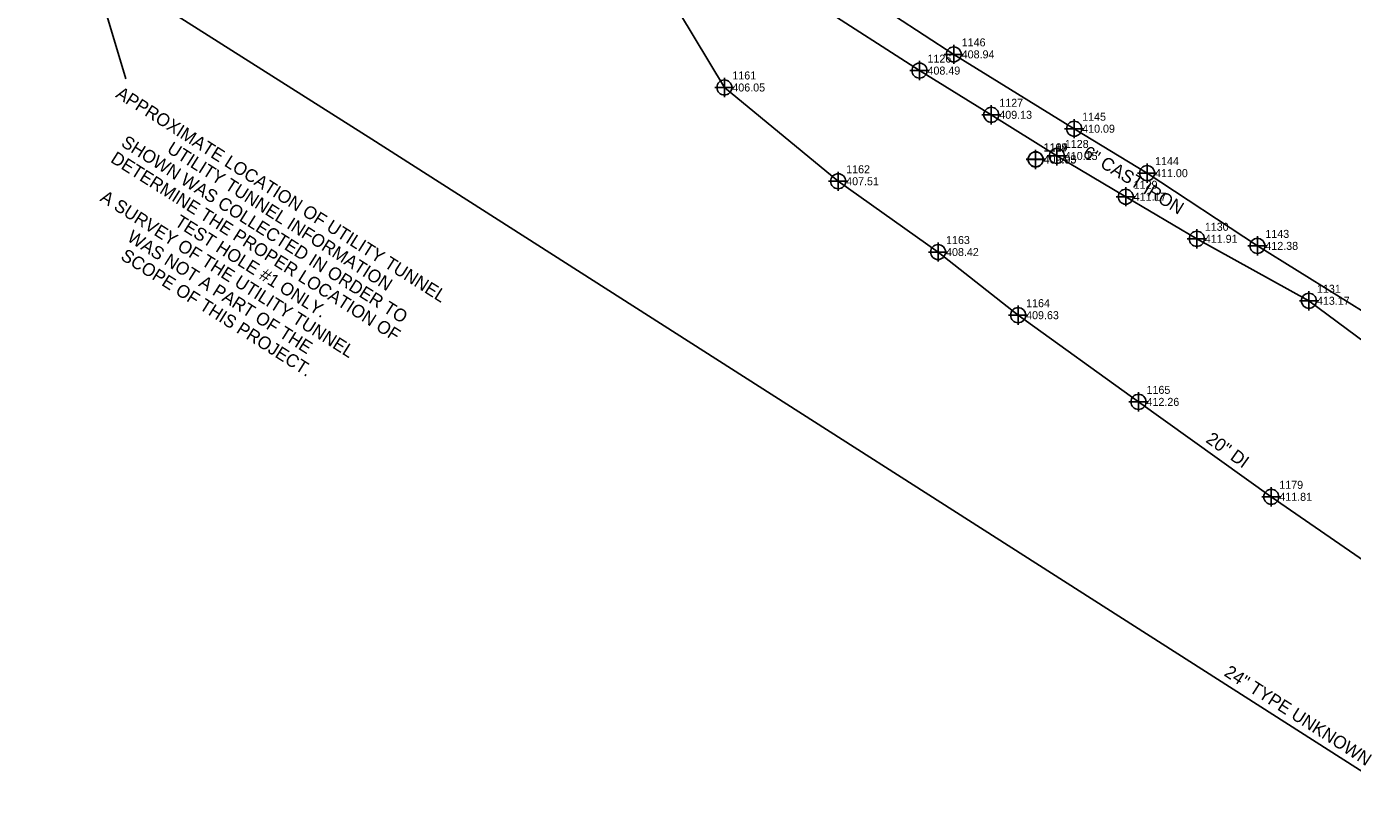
# Model space of a CAD drawing. Extents: x 2024146 to 2025516, y 819906 to 820765.
# Drawn here: x 2024645.2 to 2025059.4, y 820076.1 to 820314.8 of the extents above; entities that cross this region are included whole.
import ezdxf

# ---------------------------------------------------------------- set-up
doc = ezdxf.new("R2010")
doc.units = 0
for name, color, linetype in [('Prop Conc 4in Sidewalk', 7, 'Continuous'), ('Prop DSN Text', 7, 'Continuous'), ('Prop Lane Lines', 7, 'Continuous'), ('Sheet Block Revision CELL', 7, 'Continuous'), ('Sheet Data Field CELL', 7, 'Continuous'), ('Sheet Layout Plan Border', 7, 'Continuous'), ('Sheet Layout Profile Border Port 2', 7, 'Continuous'), ('Sheet Plan And Profile CELL', 7, 'Continuous'), ('Sheet Plot Border Inside CELL', 7, 'Continuous'), ('Sheet Plot Border Outside CELL', 7, 'Continuous'), ('Sheet Profile Grid Minor CELL', 7, 'Continuous')]:
    doc.layers.add(name, color=color, linetype=linetype)

msp = doc.modelspace()

# ---------------------------------------------------------------- linework, layer by layer
at = {"layer": 'Prop Lane Lines'}
msp.add_lwpolyline([(2024566.33, 820397.9), (2024753.12, 820279.6), (2025069.15, 820077.77), (2025141.71, 820076.11)], dxfattribs=at)
at = {"layer": 'Sheet Layout Plan Border'}
for points in [[(2024934.85, 820309.1), (2024934.85, 820306.1)], [(2024924.16, 820304.03), (2024924.16, 820301.03)], [(2024931.85, 820306.1), (2024934.85, 820306.1)], [(2024934.85, 820306.1), (2024937.85, 820306.1)], [(2024934.85, 820306.1), (2024934.85, 820303.1)], [(2024921.16, 820301.03), (2024924.16, 820301.03)], [(2024924.16, 820301.03), (2024927.16, 820301.03)], [(2024924.16, 820301.03), (2024924.16, 820298.03)], [(2024860.2, 820295.75), (2024863.2, 820295.75)], [(2024863.2, 820298.75), (2024863.2, 820295.75)], [(2024863.2, 820295.75), (2024866.2, 820295.75)], [(2024863.2, 820295.75), (2024863.2, 820292.75)], [(2024943.59, 820287.22), (2024946.59, 820287.22)], [(2024946.59, 820290.22), (2024946.59, 820287.22)], [(2024946.59, 820287.22), (2024949.59, 820287.22)], [(2024946.59, 820287.22), (2024946.59, 820284.22)], [(2024969.48, 820282.87), (2024972.48, 820282.87)], [(2024972.48, 820285.87), (2024972.48, 820282.87)], [(2024972.48, 820282.87), (2024975.48, 820282.87)], [(2024972.48, 820282.87), (2024972.48, 820279.87)], [(2024960.44, 820276.32), (2024960.44, 820273.32)], [(2024960.44, 820276.24), (2024960.44, 820273.24)], [(2024960.45, 820276.32), (2024960.45, 820273.32)], [(2024967.06, 820277.36), (2024967.06, 820274.36)], [(2024957.44, 820273.32), (2024960.44, 820273.32)], [(2024957.44, 820273.24), (2024960.44, 820273.24)], [(2024957.45, 820273.32), (2024960.45, 820273.32)], [(2024960.44, 820273.32), (2024963.44, 820273.32)], [(2024960.44, 820273.32), (2024960.44, 820270.32)], [(2024960.44, 820273.24), (2024963.44, 820273.24)], [(2024960.44, 820273.24), (2024960.44, 820270.24)], [(2024960.45, 820273.32), (2024963.45, 820273.32)], [(2024960.45, 820273.32), (2024960.45, 820270.32)], [(2024964.06, 820274.36), (2024967.06, 820274.36)], [(2024967.06, 820274.36), (2024970.06, 820274.36)], [(2024967.06, 820274.36), (2024967.06, 820271.36)], [(2024995.25, 820271.99), (2024995.25, 820268.99)], [(2024895.76, 820266.45), (2024898.76, 820266.45)], [(2024898.76, 820269.45), (2024898.76, 820266.45)], [(2024898.76, 820266.45), (2024901.76, 820266.45)], [(2024898.76, 820266.45), (2024898.76, 820263.45)], [(2024992.25, 820268.99), (2024995.25, 820268.99)], [(2024995.25, 820268.99), (2024998.25, 820268.99)], [(2024995.25, 820268.99), (2024995.25, 820265.99)], [(2024988.57, 820264.62), (2024988.57, 820261.62)], [(2024985.57, 820261.62), (2024988.57, 820261.62)], [(2024988.57, 820261.62), (2024991.57, 820261.62)], [(2024988.57, 820261.62), (2024988.57, 820258.62)], [(2025010.79, 820251.47), (2025010.79, 820248.47)], [(2024929.96, 820247.34), (2024929.96, 820244.34)], [(2025007.79, 820248.47), (2025010.79, 820248.47)], [(2025010.79, 820248.47), (2025013.79, 820248.47)], [(2025010.79, 820248.47), (2025010.79, 820245.47)], [(2025026.71, 820246.26), (2025029.71, 820246.26)], [(2025029.71, 820249.26), (2025029.71, 820246.26)], [(2025029.71, 820246.26), (2025032.71, 820246.26)], [(2025029.71, 820246.26), (2025029.71, 820243.26)], [(2024926.96, 820244.34), (2024929.96, 820244.34)], [(2024929.96, 820244.34), (2024932.96, 820244.34)], [(2024929.96, 820244.34), (2024929.96, 820241.34)], [(2025042.82, 820229.11), (2025045.82, 820229.11)], [(2025045.82, 820232.11), (2025045.82, 820229.11)], [(2025045.82, 820229.11), (2025048.82, 820229.11)], [(2025045.82, 820229.11), (2025045.82, 820226.11)], [(2024954.97, 820227.61), (2024954.97, 820224.61)], [(2024951.97, 820224.61), (2024954.97, 820224.61)], [(2024954.97, 820224.61), (2024957.97, 820224.61)], [(2024954.97, 820224.61), (2024954.97, 820221.61)], [(2024992.58, 820200.53), (2024992.58, 820197.53)], [(2024989.58, 820197.53), (2024992.58, 820197.53)], [(2024992.58, 820197.53), (2024995.58, 820197.53)], [(2024992.58, 820197.53), (2024992.58, 820194.53)], [(2025034.06, 820170.86), (2025034.06, 820167.86)], [(2025031.06, 820167.86), (2025034.06, 820167.86)], [(2025034.06, 820167.86), (2025037.06, 820167.86)], [(2025034.06, 820167.86), (2025034.06, 820164.86)]]:
    msp.add_lwpolyline(points, dxfattribs=at)
for centre in [(2024934.85, 820306.1), (2024924.16, 820301.03), (2024863.2, 820295.75), (2024946.59, 820287.22), (2024972.48, 820282.87), (2024960.44, 820273.32), (2024960.45, 820273.32), (2024960.44, 820273.24), (2024967.06, 820274.36), (2024995.25, 820268.99), (2024898.76, 820266.45), (2024988.57, 820261.62), (2025010.79, 820248.47), (2024929.96, 820244.34), (2025029.71, 820246.26), (2025045.82, 820229.11), (2024954.97, 820224.61), (2024992.58, 820197.53), (2025034.06, 820167.86)]:
    msp.add_circle(centre, 2.34, dxfattribs=at)
at = {"layer": 'Sheet Plan And Profile CELL'}
for points in [[(2024814.33, 820367.34), (2024832.46, 820347.9), (2024844.26, 820327.26), (2024863.2, 820295.75), (2024898.76, 820266.45), (2024929.96, 820244.34), (2024954.97, 820224.61), (2024992.58, 820197.53)], [(2024826.71, 820365.84), (2024835.33, 820357.93), (2024866.41, 820337.18), (2024892.38, 820321.46), (2024924.16, 820301.03), (2024946.59, 820287.22), (2024967.06, 820274.36), (2024988.57, 820261.62), (2025010.79, 820248.47), (2025045.82, 820229.11), (2025063.46, 820215.95), (2025102.86, 820187.61), (2025131, 820170.89), (2025157.73, 820152.25), (2025180.55, 820137.37)], [(2025034.06, 820167.86), (2024992.58, 820197.53)], [(2025034.06, 820167.86), (2025072.24, 820141.49)]]:
    msp.add_lwpolyline(points, dxfattribs=at)
at = {"layer": 'Sheet Plot Border Inside CELL'}
msp.add_lwpolyline([(2024662, 820346.17), (2024676.28, 820298.43)], dxfattribs=at)
at = {"layer": 'Sheet Profile Grid Minor CELL'}
msp.add_lwpolyline([(2024781.27, 820403.16), (2024814.31, 820383.67), (2024841.03, 820366.91), (2024897.86, 820330.32), (2024934.85, 820306.1), (2024972.48, 820282.87), (2024995.25, 820268.99), (2025029.71, 820246.26), (2025066.92, 820223.12), (2025091.61, 820207.05), (2025109.4, 820196), (2025136.22, 820178.55), (2025163.27, 820161.2)], dxfattribs=at)

# ---------------------------------------------------------------- texts
at = {"layer": 'Prop Conc 4in Sidewalk'}
msp.add_text('6" CAST IRON', height=4, rotation=328.625, dxfattribs=at).set_placement((2024974.86, 820274.39))
at = {"layer": 'Prop DSN Text'}
msp.add_text('24" TYPE UNKNOWN', height=4, rotation=327.4366, dxfattribs=at).set_placement((2025019.03, 820112.15))
at = {"layer": 'Sheet Block Revision CELL'}
for s, p in [('1146', (2024937.35, 820308.6)), ('1126', (2024926.66, 820303.53)), ('1161', (2024865.7, 820298.25)), ('1127', (2024949.09, 820289.72)), ('1145', (2024974.98, 820285.37)), ('1128', (2024969.56, 820276.86)), ('1104', (2024962.94, 820275.82)), ('1169', (2024962.95, 820275.82)), ('1117', (2024962.94, 820275.74)), ('1162', (2024901.26, 820268.95)), ('1144', (2024997.75, 820271.49)), ('1129', (2024991.07, 820264.12)), ('1130', (2025013.29, 820250.97)), ('1143', (2025032.21, 820248.76)), ('1163', (2024932.46, 820246.84)), ('1131', (2025048.32, 820231.61)), ('1164', (2024957.47, 820227.11)), ('1165', (2024995.08, 820200.03)), ('1179', (2025036.56, 820170.36))]:
    msp.add_text(s, height=2.5, dxfattribs=at).set_placement(p)
at = {"layer": 'Sheet Data Field CELL'}
msp.add_text('20" DI', height=4, rotation=324.4223, dxfattribs=at).set_placement((2025013.33, 820185.15))
at = {"layer": 'Sheet Layout Profile Border Port 2'}
for s, p in [('408.94', (2024937.35, 820304.85)), ('408.49', (2024926.66, 820299.78)), ('406.05', (2024865.7, 820294.5)), ('409.13', (2024949.09, 820285.97)), ('410.09', (2024974.98, 820281.62)), ('409.95', (2024962.94, 820272.07)), ('409.93', (2024962.95, 820272.07)), ('409.95', (2024962.94, 820271.99)), ('410.15', (2024969.56, 820273.11)), ('411.00', (2024997.75, 820267.74)), ('407.51', (2024901.26, 820265.2)), ('411.17', (2024991.07, 820260.37)), ('411.91', (2025013.29, 820247.22)), ('408.42', (2024932.46, 820243.09)), ('412.38', (2025032.21, 820245.01)), ('413.17', (2025048.32, 820227.86)), ('409.63', (2024957.47, 820223.36)), ('412.26', (2024995.08, 820196.28)), ('411.81', (2025036.56, 820166.61))]:
    msp.add_text(s, height=2.5, dxfattribs=at).set_placement(p)
at = {"layer": 'Sheet Plot Border Outside CELL'}
for s, p in [('APPROXIMATE LOCATION OF UTILITY TUNNEL', (2024672.78, 820292.9)), ('SHOWN WAS COLLECTED IN ORDER TO', (2024674.46, 820277.64)), ('UTILITY TUNNEL INFORMATION', (2024688.79, 820275.68)), ('DETERMINE THE PROPER LOCATION OF', (2024671.17, 820272.62)), ('A SURVEY OF THE UTILITY TUNNEL', (2024667.9, 820260.5)), ('TEST HOLE #1 ONLY.', (2024691.2, 820252.85)), ('WAS NOT A PART OF THE', (2024676.34, 820248.06)), ('SCOPE OF THIS PROJECT.', (2024674.31, 820242.24))]:
    msp.add_text(s, height=4, rotation=327.6834, dxfattribs=at).set_placement(p)

doc.saveas('drawing.dxf')
